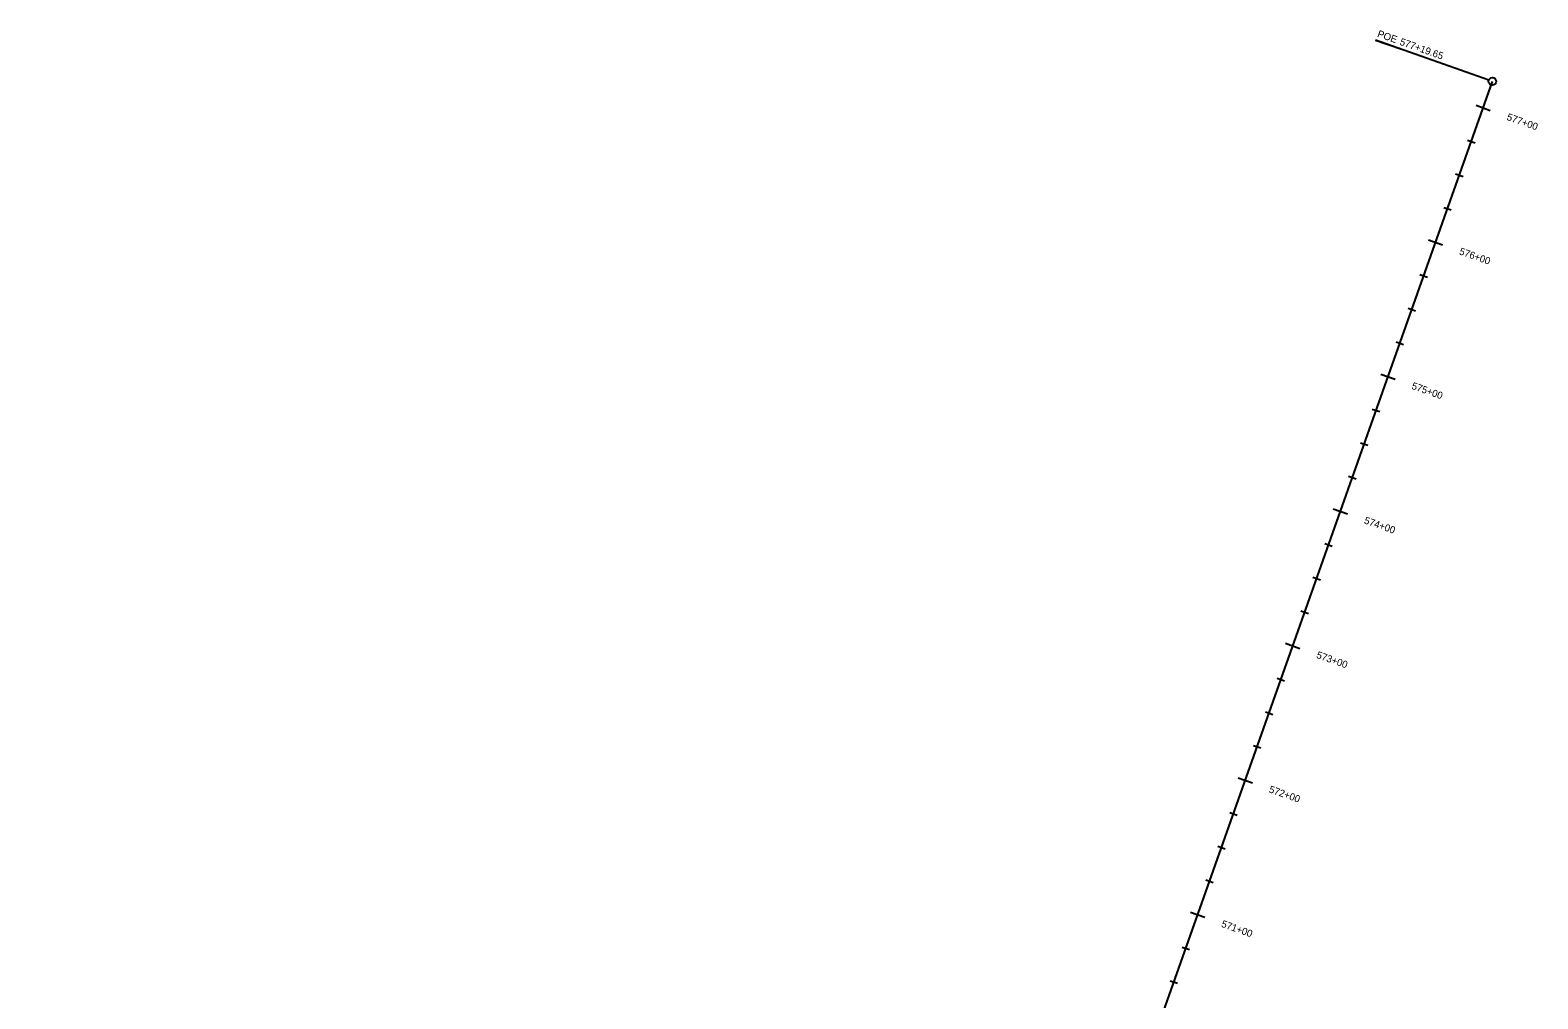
# Model space of a CAD drawing. Extents: x 2300830 to 2307917, y 756066 to 766359.
# Drawn here: x 2304442 to 2305499, y 765680 to 766359 of the extents above; entities that cross this region are included whole.
import ezdxf

# ---------------------------------------------------------------- set-up
doc = ezdxf.new("R2010")
doc.units = 0
for name, color, linetype in [('Default', 7, 'Continuous'), ('Draft_Station Cardinal Points', 7, 'Continuous'), ('Draft_Station Labels Major', 7, 'Continuous'), ('Draft_Station Ticks Major', 7, 'Continuous'), ('Draft_Station Ticks Minor', 7, 'Continuous'), ('Geom_Baseline', 7, 'Continuous')]:
    doc.layers.add(name, color=color, linetype=linetype)

msp = doc.modelspace()

# ---------------------------------------------------------------- linework, layer by layer
at = {"layer": 'Default'}
msp.add_line((2304441.8, 763425), (2305466.9, 766322.6), dxfattribs=at)
at = {"layer": 'Draft_Station Cardinal Points'}
for p, q in [((2305464.4, 766323.5), (2305384.9, 766351.6)), ((2305384.9, 766351.6), (2305403.5, 766345.1)), ((2305466.9, 766322.6), (2305466.9, 766322.6))]:
    msp.add_line(p, q, dxfattribs=at)
msp.add_circle((2305466.9, 766322.6), 2.67, dxfattribs=at)
at = {"layer": 'Draft_Station Ticks Major'}
for p, q in [((2305455.4, 766305.9), (2305465.4, 766302.3)), ((2305422, 766211.6), (2305432, 766208.1)), ((2305388.6, 766117.3), (2305398.7, 766113.8)), ((2305355.3, 766023.1), (2305365.3, 766019.5)), ((2305321.9, 765928.8), (2305331.9, 765925.2)), ((2305288.6, 765834.5), (2305298.6, 765831)), ((2305255.2, 765740.2), (2305265.2, 765736.7))]:
    msp.add_line(p, q, dxfattribs=at)
at = {"layer": 'Draft_Station Ticks Minor'}
for p, q in [((2305449.4, 766281.4), (2305454.7, 766279.6)), ((2305441.1, 766257.9), (2305446.3, 766256)), ((2305432.8, 766234.3), (2305438, 766232.5)), ((2305416.1, 766187.2), (2305421.3, 766185.3)), ((2305407.8, 766163.6), (2305413, 766161.8)), ((2305399.4, 766140), (2305404.6, 766138.2)), ((2305382.7, 766092.9), (2305387.9, 766091.1)), ((2305374.4, 766069.3), (2305379.6, 766067.5)), ((2305366.1, 766045.8), (2305371.3, 766043.9)), ((2305349.4, 765998.6), (2305354.6, 765996.8)), ((2305341, 765975.1), (2305346.3, 765973.2)), ((2305332.7, 765951.5), (2305337.9, 765949.6)), ((2305316, 765904.3), (2305321.2, 765902.5)), ((2305307.7, 765880.8), (2305312.9, 765878.9)), ((2305299.4, 765857.2), (2305304.6, 765855.4)), ((2305282.7, 765810.1), (2305287.9, 765808.2)), ((2305274.3, 765786.5), (2305279.5, 765784.7)), ((2305266, 765762.9), (2305271.2, 765761.1)), ((2305249.3, 765715.8), (2305254.5, 765714)), ((2305241, 765692.2), (2305246.2, 765690.4))]:
    msp.add_line(p, q, dxfattribs=at)
at = {"layer": 'Geom_Baseline'}
msp.add_line((2304441.8, 763425), (2305466.9, 766322.6), dxfattribs=at)

# ---------------------------------------------------------------- texts
at = {"layer": 'Draft_Station Cardinal Points'}
for s, p in [('POE ', (2305385.8, 766354)), ('577+19.65', (2305401.5, 766348.4))]:
    msp.add_text(s, height=5, rotation=340.5164, dxfattribs=at).set_placement(p)
at = {"layer": 'Draft_Station Labels Major'}
for s, p in [('577+00', (2305476.5, 766295.7)), ('576+00', (2305443.2, 766201.5)), ('575+00', (2305409.8, 766107.2)), ('574+00', (2305376.5, 766012.9)), ('573+00', (2305343.1, 765918.6)), ('572+00', (2305309.8, 765824.4)), ('571+00', (2305276.4, 765730.1))]:
    msp.add_text(s, height=5, rotation=340.5164, dxfattribs=at).set_placement(p)

doc.saveas('drawing.dxf')
